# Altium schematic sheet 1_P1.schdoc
size 309 x 223 mm; Symbol: Sheet-Symbol_A4; Device: Sheet-Symbol_A4; @Page Name: P1; @Create Date: 2023-06-18; @Page Count: 1; @Page No: 1; @Project Name: usrp2040-series; @Schematic Name: wPlatform education; @Update Date: 2023-06-22; Company: 嘉立创EDA; Page Size: A4; Version: V1.0
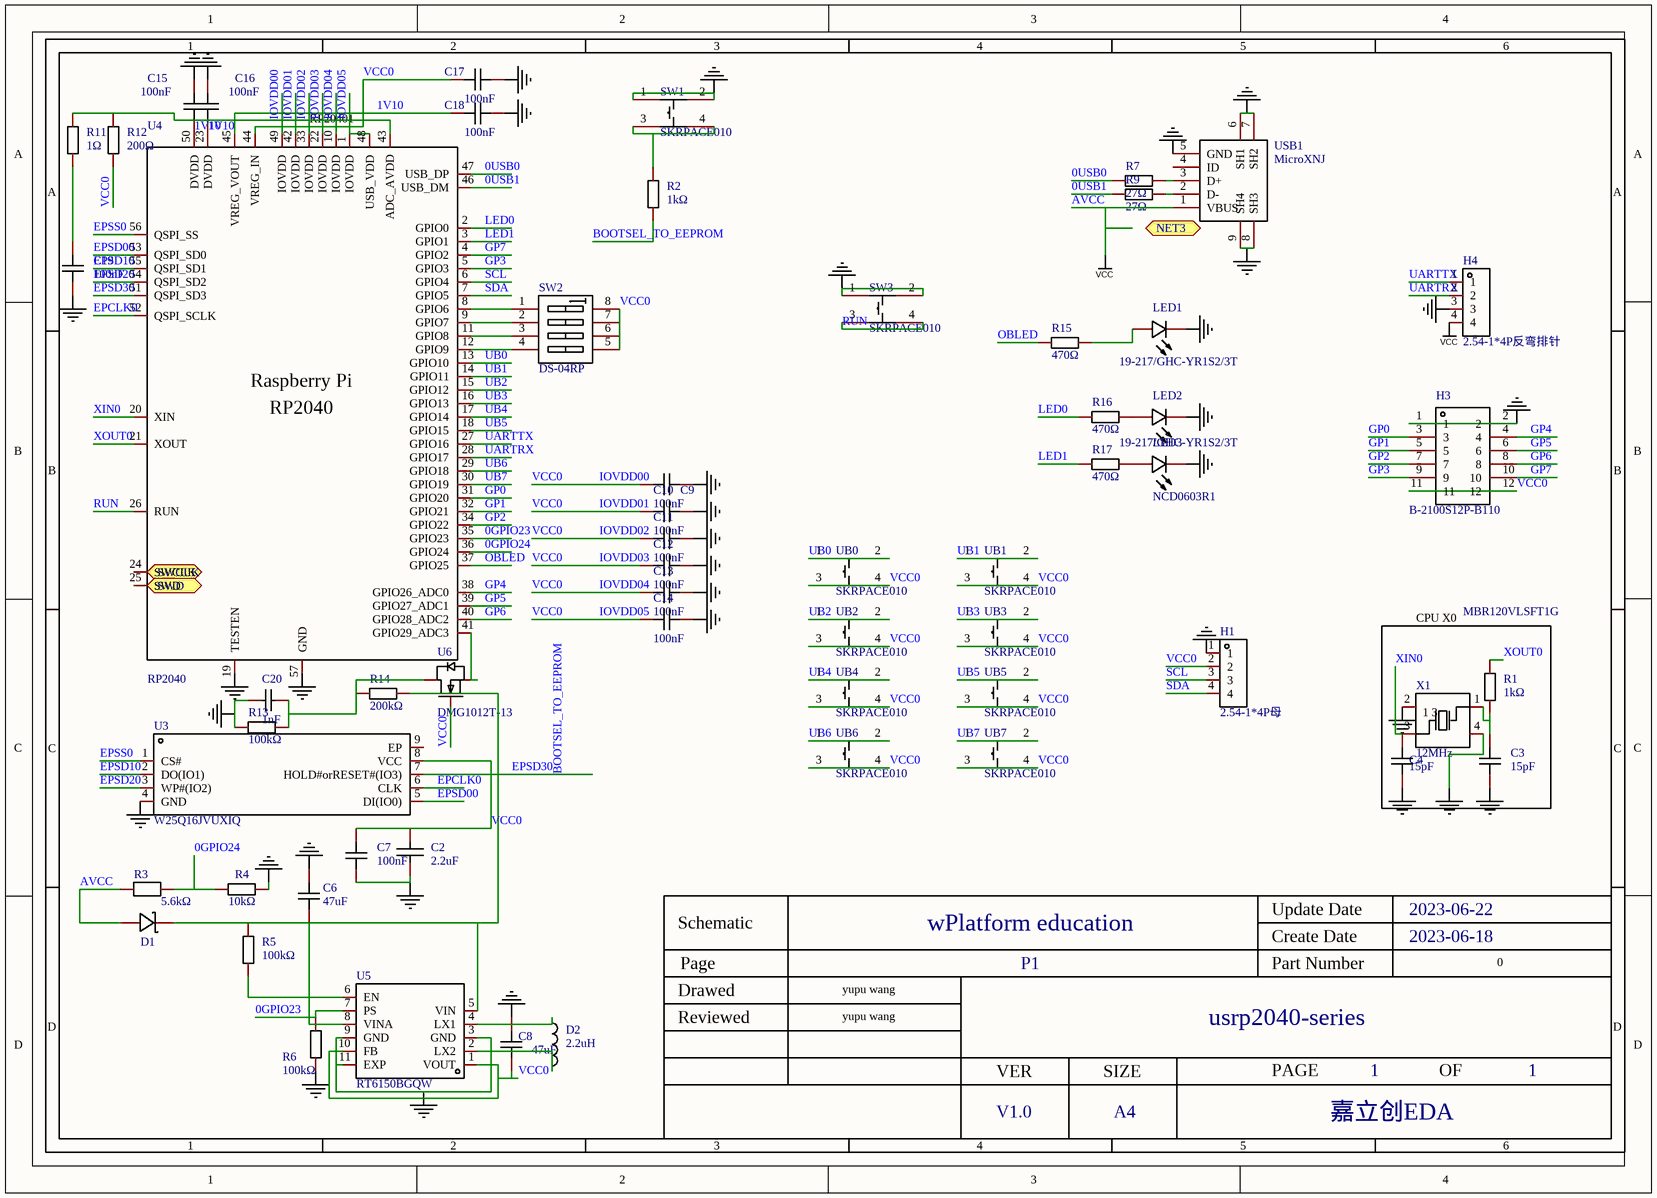
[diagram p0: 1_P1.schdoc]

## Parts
C2  2.2uF  [C0402]
C3  15pF  [C0201]
C4  15pF  [C0201]
C6  47uF  [C0805]
C7  100nF  [C0201]
C8  47uF  [C0805]
C9  100nF  [C0201]
C10  100nF  [C0201]
C11  100nF  [C0201]
C12  100nF  [C0201]
C13  100nF  [C0201]
C14  100nF  [C0201]
C15  100nF  [C0201]
C16  100nF  [C0201]
C17  100nF  [C0201]
C18  100nF  [C0201]
C19  100nF  [C0201]
C20  1nF  [C0201]
D1  MBR120VLSFT1G  [SOD-123F_L2.8-W1.8-LS3.7-RD]
D2  2.2uH  [IND-SMD_L2.5-W2.0]
H1  2.54-1*4P母  [HDR-TH_4P-P2.54-V-F]
H3  B-2100S12P-B110  [HDR-TH_12P-P2.54-V-M-R2-C6-S2.54]
H4  2.54-1*4P反弯排针  [HDR-TH_4P-P2.54-H-M-W10.4]
LED1  19-217/GHC-YR1S2/3T  [LED0603-RD]
LED2  19-217/GHC-YR1S2/3T  [LED0603-RD]
LED3  NCD0603R1  [LED0603-RD_RED]
R1  1kΩ  [R0402]
R2  1kΩ  [R0402]
R3  5.6kΩ  [R0402]
R4  10kΩ  [R0603]
R5  100kΩ  [R0402]
R6  100kΩ  [R0402]
R7  27Ω  [R0201]
R9  27Ω  [R0201]
R11  1Ω  [R0402]
R12  200Ω  [R0603]
R13  100kΩ  [R0402]
R14  200kΩ  [R0402]
R15  470Ω  [R0402]
R16  470Ω  [R0402]
R17  470Ω  [R0402]
SW1  SKRPACE010  [KEY-SMD_4P-L4.2-W3.2-P2.20-LS4.6]
SW2  DS-04RP  [SW-TH_DS-04XP]
SW3  SKRPACE010  [KEY-SMD_4P-L4.2-W3.2-P2.20-LS4.6]
U3  W25Q16JVUXIQ  [USON-8_L3.0-W2.0-P0.50-BL-EP]
U4  RP2040  [LQFN-56_L7.0-W7.0-P0.4-EP]
U5  RT6150BGQW  [WSON-10_L2.5-W2.5-P0.50-BL-EP]
U6  DMG1012T-13  [SOT-523-3_L1.6-W0.8-P1.00-LS1.6-BR]
UB0  SKRPACE010  [KEY-SMD_4P-L4.2-W3.2-P2.20-LS4.6]
UB1  SKRPACE010  [KEY-SMD_4P-L4.2-W3.2-P2.20-LS4.6]
UB2  SKRPACE010  [KEY-SMD_4P-L4.2-W3.2-P2.20-LS4.6]
UB3  SKRPACE010  [KEY-SMD_4P-L4.2-W3.2-P2.20-LS4.6]
UB4  SKRPACE010  [KEY-SMD_4P-L4.2-W3.2-P2.20-LS4.6]
UB5  SKRPACE010  [KEY-SMD_4P-L4.2-W3.2-P2.20-LS4.6]
UB6  SKRPACE010  [KEY-SMD_4P-L4.2-W3.2-P2.20-LS4.6]
UB7  SKRPACE010  [KEY-SMD_4P-L4.2-W3.2-P2.20-LS4.6]
USB1  MicroXNJ  [MICRO-USB-SMD_MICROXNJ]
X1  12MHz  [CRYSTAL-SMD_4P-L3.2-W2.5-BL]

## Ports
NET3 (bidir), SWCLK (bidir), SWD (bidir)

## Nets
AVCC: D1.2(A) H4.4 R3.2 USB1.1(VBUS)  [also labelled VCC]
NetC2_2: C2.2 C3.1 C4.1 C6.1 C7.1 C8.2 C9.2 C10.2 C11.2 C12.2 C13.2 C14.2 C15.1 C16.2 C17.1 C18.1 C19.1 C20.1 H1.1 H3.1 H3.2 H4.3 LED1.1(C) LED2.1(C) LED3.1(K) R4.2 R6.1 R13.1 SW1.1 SW1.2 SW3.1 SW3.2 U3.4(GND) U4.19(TESTEN) U4.57(GND) U5.3(GND) U5.9(GND) U5.11(EXP) USB1.5(GND) USB1.6(SH1) USB1.7(SH2) USB1.8(SH3) USB1.9(SH4) X1.2(GND) X1.4(GND)
0GPIO23: R6.2 U4.35(GPIO23) U5.7(PS)
0GPIO24: R3.1 R4.1 U4.36(GPIO24)
0USB0: R7.1 U4.47(USB_DP)
0USB1: R9.1 U4.46(USB_DM)
1V10: C15.2 C16.1 C18.2 U4.23(DVDD) U4.45(VREG_VOUT) U4.50(DVDD)
BOOTSEL_TO_EEPROM: R2.1 U3.7(HOLD#orRESET#(IO3)) U4.51(QSPI_SD3)  [also labelled EPSD30]
EPCLK0: U3.6(CLK) U4.52(QSPI_SCLK)
EPSD00: U3.5(DI(IO0)) U4.53(QSPI_SD0)
EPSD10: U3.2(DO(IO1)) U4.55(QSPI_SD1)
EPSD20: U3.3(WP#(IO2)) U4.54(QSPI_SD2)
EPSS0: U3.1(CS#) U4.56(QSPI_SS)
GP0: H3.3 U4.31(GPIO20)
GP1: H3.5 U4.32(GPIO21)
GP2: H3.7 U4.34(GPIO22)
GP3: H3.9 U4.5(GPIO3)
GP4: H3.4 U4.38(GPIO26_ADC0)
GP5: H3.6 U4.39(GPIO27_ADC1)
GP6: H3.8 U4.40(GPIO28_ADC2)
GP7: H3.10 U4.4(GPIO2)
IOVDD00: C2.1 C7.2 C8.1 C9.1 C10.1 C11.1 C12.1 C13.1 C14.1 C17.2 H1.2 H3.11 H3.12 R11.2 R12.1 R12.2 SW2.5 SW2.6 SW2.7 SW2.8 U3.8(VCC) U4.1(IOVDD) U4.10(IOVDD) U4.22(IOVDD) U4.33(IOVDD) U4.42(IOVDD) U4.43(ADC_AVDD) U4.44(VREG_IN) U4.48(USB_VDD) U4.49(IOVDD) U5.1(VOUT) U5.10(FB) U6.1(G) UB0.3 UB0.4 UB1.3 UB1.4 UB2.3 UB2.4 UB3.3 UB3.4 UB4.3 UB4.4 UB5.3 UB5.4 UB6.3 UB6.4 UB7.3 UB7.4  [also labelled IOVDD01, IOVDD02, IOVDD03, IOVDD04, IOVDD05, VCC0]
LED0: R16.1 U4.2(GPIO0)
LED1: R17.1 U4.3(GPIO1)
OBLED: R15.1 U4.37(GPIO25)
RUN: SW3.3 SW3.4 U4.26(RUN)
SCL: H1.3 U4.6(GPIO4)
SDA: H1.4 U4.7(GPIO5)
UARTRX: H4.2 U4.28(GPIO17)
UARTTX: H4.1 U4.27(GPIO16)
UB0: U4.13(GPIO10) UB0.1 UB0.2
UB1: U4.14(GPIO11) UB1.1 UB1.2
UB2: U4.15(GPIO12) UB2.1 UB2.2
UB3: U4.16(GPIO13) UB3.1 UB3.2
UB4: U4.17(GPIO14) UB4.1 UB4.2
UB5: U4.18(GPIO15) UB5.1 UB5.2
UB6: U4.29(GPIO18) UB6.1 UB6.2
UB7: U4.30(GPIO19) UB7.1 UB7.2
XIN0: C4.2 U4.20(XIN) X1.3(OSC2)
XOUT0: R1.2 U4.21(XOUT)
NetC3_2: C3.2 R1.1 X1.1(OSC1)
NetC6_2: C6.2 D1.1(K) R5.2 R14.2 U5.5(VIN) U5.8(VINA)
NetC19_2: C19.2 R11.1
NetC20_2: C20.2 R13.2 R14.1 U6.3(D)
NetD2_1: D2.1 U5.4(LX1)
NetD2_2: D2.2 U5.2(LX2)
NetLED1_2: LED1.2(A) R15.2
NetLED2_2: LED2.2(A) R16.2
NetLED3_2: LED3.2(A) R17.2
NetR2_2: R2.2 SW1.3 SW1.4
NetR5_1: R5.1 U5.6(EN)
NetR7_2: R7.2 USB1.3(D+)
NetR9_2: R9.2 USB1.2(D-)
NetSW2_1: SW2.1(A1) U4.8(GPIO6)
NetSW2_2: SW2.2(A2) U4.9(GPIO7)
NetSW2_3: SW2.3(A3) U4.11(GPIO8)
NetSW2_4: SW2.4(A4) U4.12(GPIO9)
NetU4_41: U4.41(GPIO29_ADC3) U6.2(S)

Not connected (* = marked no-connect by the designer): U3 9(EP); U4 24(SWCLK) 25(SWD); USB1 4(ID)

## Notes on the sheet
- (near U4) RP20401
- CPU X0
- (near X1) 1 3
- yupu wang
- 0

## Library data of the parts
C2 = CL05A225MQ5NSNC: 容值:2.2uF;精度:±20%;额定电压:6.3V;材质(温度系数):X5R;; Manufacturer: SAMSUNG(三星); Add into BOM: yes; Tolerance: ±20%; Voltage Rated: 6.3V; Temperature Coefficient: X5R
C3 C4 = CL03C150JA3ANNC: 容值:15pF;精度:±5%;额定电压:25V;材质(温度系数):C0G;; Manufacturer: SAMSUNG(三星); Add into BOM: yes; Tolerance: ±5%; Voltage Rated: 25V; Temperature Coefficient: C0G
C6 C8 = GRM21BR60J476ME01L: 容值:47uF;精度:±20%;额定电压:6.3V;材质(温度系数):X5R;; Manufacturer: muRata(村田); Add into BOM: yes; Tolerance: ±20%; Voltage Rated: 6.3V; Temperature Coefficient: X5R
C7 C9-C19 = GRM033R60J104KE19D: 容值:100nF;精度:±10%;额定电压:6.3V;材质(温度系数):X5R;; Manufacturer: muRata(村田); Add into BOM: yes; Tolerance: ±10%; Voltage Rated: 6.3V; Temperature Coefficient: X5R
C20 = GRM033R71E102KA01D: 容值:1nF;精度:±10%;额定电压:25V;材质(温度系数):X7R;; Manufacturer: muRata(村田); Add into BOM: yes; Tolerance: ±10%; Voltage Rated: 25V; Temperature Coefficient: X7R
D1 = MBR120VLSFT1G: 直流反向耐压(Vr):20V;平均整流电流(Io):1A;正向压降(Vf):300mV@1A;; Manufacturer: onsemi(安森美); Add into BOM: yes; Reverse Voltage (Vr): 20V; Average Rectified Current (Io): 1A
D2 = SRN2512-2R2M: 电感值:2.2uH;精度:±20%;额定电流:2.3A;饱和电流(Isat):2.7A;直流电阻(DCR):102mΩ;; Manufacturer: BOURNS; Add into BOM: yes; Tolerance: ±20%; Rated Current: 2.3A; Saturation Current (Isat): 2.7A; DC Resistance (DCR): 102mΩ; Q @ Freq: 11@1MHz; Frequency - Self Resonant: 80MHz
H1 = 2.54-1*4P母: 排数:单排;总孔位数:4;间距:2.54mm;插孔结构:1x4P;行距:-;安装类型:直插;圆孔/方孔:方孔;额定电流:3A;额定电压:-;插孔方向:顶部;塑高:-;触头材质:青铜;触头镀层:-;工作温度范围:-40℃~+105℃;焊接温度(最大值):-;; Manufacturer: BOOMELE(博穆精密); Add into BOM: yes; Number of Holes: 4; Pitch: 2.54mm; Holes Structure: 1x4P; Circular Hole / Square Hole: 方孔; Current Rating (Max): 3A; Holes Direction: 顶部
H3 = B-2100S12P-B110: 排数:双排;总PIN位数:12;间距:2.54mm;插针结构:2x6P;行距:2.54mm;安装类型:直插;圆针/方针:-;额定电流:-;额定电压:-;配合针长度:6mm;塑高:2.54mm;端接针长度:3mm;触头材质:黄铜;触头镀层:-;工作温度范围:-40℃~+105℃;颜色:黑色;; Manufacturer: Ckmtw(灿科盟); Symbol: 210S-2*6P L=11.6MMGold-plated black; Add into BOM: yes; Pitch: 2.54mm; Pin Structure: 2x6P
H4 = 2.54-1*4P反弯排针: 排数:单排;总PIN位数:4;间距:2.54mm;插针结构:1x4P;行距:-;安装类型:弯插;圆针/方针:方针;额定电流:3A;额定电压:-;配合针长度:6mm;塑高:-;端接针长度:-;触头材质:-;触头镀层:-;工作温度范围:-55℃~+105℃;颜色:黑色;; Manufacturer: BOOMELE(博穆精密); Add into BOM: yes; Pitch: 2.54mm; Pin Structure: 1x4P; Circluar Pins/Square Pins: 方针; Current Rating (Max): 3A
LED1 LED2 = 19-217/GHC-YR1S2/3T: 发光颜色:翠绿;二极管配置:-;主波长:520nm~535nm;色温:-;功率:110mW;安装方式:-;; Manufacturer: EVERLIGHT(亿光); Add into BOM: yes; Emitted Color: 翠绿; Lens Color: 无色透明; Peak Wavelength: 518nm; Forward Current: 20mA; Power Dissipation: 110mW; Viewing Angle: 120°
LED3 = NCD0603R1_C84263: 发光颜色:红灯;; Manufacturer: 国星光电; Symbol: FC-DA1608HRK-620D; Add into BOM: yes; Emitted Color: 红灯
R1 R2 = AECR0402F1K00K9: 电阻类型:厚膜电阻;阻值:1kΩ;精度:±1%;功率:63mW;; Manufacturer: RESI(开步睿思）; Add into BOM: yes; Tolerance: ±1%; Power(Watts): 63mW; Temperature Coefficient: ±100ppm/℃; Overload Voltage (Max): 50V
R3 = CR0402F5K60Q10Z: 阻值:5.6kΩ;精度:±1%;功率:63mW;; Manufacturer: EVER OHMS(天二科技); Add into BOM: yes; Tolerance: ±1%; Power(Watts): 63mW; Temperature Coefficient: ±100ppm/℃
R4 = 0603WAF1002T5E: 电阻类型:厚膜电阻;阻值:10kΩ;精度:±1%;功率:100mW;; Manufacturer: UNI-ROYAL(厚声); Add into BOM: yes; Tolerance: ±1%; Power(Watts): 100mW; Temperature Coefficient: ±100ppm/℃; Overload Voltage (Max): 75V
R5 R6 R13 = RC0402FR-07100KL: 电阻类型:厚膜电阻;阻值:100kΩ;精度:±1%;功率:62.5mW;; Manufacturer: YAGEO(国巨); Add into BOM: yes; Tolerance: ±1%; Power(Watts): 62.5mW; Temperature Coefficient: ±100ppm/℃; Overload Voltage (Max): 50V
R7 R9 = RC0201FR-0727RL: 电阻类型:厚膜电阻;阻值:27Ω;精度:±1%;功率:50mW;; Manufacturer: YAGEO(国巨); Add into BOM: yes; Tolerance: ±1%; Power(Watts): 50mW; Temperature Coefficient: ±200ppm/℃; Overload Voltage (Max): 25V
R11 = RC0402FR-071RL: 电阻类型:厚膜电阻;阻值:1Ω;精度:±1%;功率:62.5mW;; Manufacturer: YAGEO(国巨); Add into BOM: yes; Tolerance: ±1%; Power(Watts): 62.5mW; Temperature Coefficient: ±200ppm/℃; Overload Voltage (Max): 50V
R12 = RC0603FR-07200RL: 电阻类型:厚膜电阻;阻值:200Ω;精度:±1%;功率:100mW;; Manufacturer: YAGEO(国巨); Add into BOM: yes; Tolerance: ±1%; Power(Watts): 100mW; Temperature Coefficient: ±100ppm/℃; Overload Voltage (Max): 75V
R14 = RC0402FR-07200KL: 电阻类型:厚膜电阻;阻值:200kΩ;精度:±1%;功率:62.5mW;; Manufacturer: YAGEO(国巨); Add into BOM: yes; Tolerance: ±1%; Power(Watts): 62.5mW; Temperature Coefficient: ±100ppm/℃; Overload Voltage (Max): 50V
R15-R17 = RC0402FR-07470RL: 电阻类型:厚膜电阻;阻值:470Ω;精度:±1%;功率:62.5mW;; Manufacturer: YAGEO(国巨); Add into BOM: yes; Tolerance: ±1%; Power(Watts): 62.5mW; Temperature Coefficient: ±100ppm/℃; Overload Voltage (Max): 50V
SW1 SW3 UB0-UB7 = SKRPACE010: 触点电流:50mA;额定电压(DC):16V;电路结构:单刀单掷;安装方式:立贴;带灯:-;机械寿命:-;; Manufacturer: ALPSALPINE(阿尔卑斯阿尔派); Add into BOM: yes; Contact Current: 50mA; Voltage Rating (DC): 16V; Circuit: 单刀单掷; Actuator Style: 椭圆形按钮; Switch Length: 4.2mm; Switch Width: 3.2mm; Switch Height: 2.5mm
SW2 = DS-04RP_C319060: 类型:平拨，凸起式;额定电流:25mA;额定电压:24V;电路结构:单刀单掷;开关位数:4;使用寿命:3千次;颜色:红色;; Manufacturer: XKB Connectivity(中国星坤); Add into BOM: yes; Current Rating: 25mA; Voltage Rating: 24V; Circuit: 单刀单掷; Number of Positions: 4; Pin Style: PC引脚; Operating Life: 3千次
U3 = W25Q16JVUXIQ: Manufacturer: WINBOND(华邦); Add into BOM: no; Convert to PCB: yes
U4 = RP2040_C2040: 应用领域:-;CPU内核:ARM-M系列;CPU最大主频:133MHz;工作电压范围:-;程序存储容量:-;程序存储器类型:-;RAM总容量:264KB;GPIO端口数量:30;; Manufacturer: Raspberry Pi(树莓派); Add into BOM: no; Convert to PCB: yes; CPU Maximum Speed: 133MHz; RAM Size: 264KB; GPIO Ports Number: 30; ADC (Bit): 12bit; UART/USART: 2; Universal Serial Bus: 有; Peripheral/Function: DMA；PWM
U5 = RT6150BGQW: 功能类型:升降压型;同步整流:是;输出通道数:1;拓扑结构:降压-升压式;输入电压:1.8V~5.5V;输出电压:1.8V~5.5V;输出电流(最大值):800mA;开关频率:1MHz;; Manufacturer: RICHTEK(立锜); Add into BOM: yes; Function: 升降压型; Synchronous Rectification: 是; Number of Outputs: 1; Topology: 降压-升压式; Output Current (Max): 800mA; Switching Frequency: 1MHz
U6 = DMG1012T-13: 类型:N沟道;漏源电压(Vdss):20V;连续漏极电流(Id):630mA;功率(Pd):280mW;导通电阻(RDS(on)@Vgs,Id):400mΩ@600mA,4.5V;; Manufacturer: DIODES(美台); Add into BOM: yes; Drain Source Voltage (Vdss): 20V; Continuous Drain Current (Id): 630mA; Power Dissipation (Pd): 280mW; Gate Threshold Voltage (Vgs(th)@Id): 1V@250uA; Total Gate Charge (Qg@Vgs): 737pC@4.5V; Input Capacitance (Ciss@Vds): 60.67pF@16V
USB1 = MicroXNJ: 连接器类型:Micro-B;标准:USB 2.0;公母:母座;触点数量:5;端口数量:1;安装方式:卧贴;额定电流 - 电源:1A;工作温度范围:-20℃~+85℃;; Manufacturer: SHOU HAN(首韩); Add into BOM: yes; Gender: 母座; Number of Contacts: 5; Number of Ports: 1; Current Rating - Power (Max): 1A
X1 = X322512MMB4SI: 频率:12MHz;频率公差:±10ppm;负载电容:10pF;; Manufacturer: YXC(扬兴晶振); Add into BOM: yes; Crystal Type: 贴片无源晶振; Frequency Tolerance: ±10ppm; Frequency Stability: ±30ppm; Load Capacitance: 10pF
